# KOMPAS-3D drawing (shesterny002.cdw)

Views: View = Шестерня, Вид слева, Разрез Б-Б, Вид 12, Вид 13, Выносной элемент, Вид 16, Вид 17
Referenced files in C:\Program Files (x86)\ASCON\KOMPAS-3D V12\Sys\: spds.lcs
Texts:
  Шестерня
  Торцы зубъев закруглить
  Делительный диаметр
  Длина общей нормали
  Степень точности
  по ГОСТ 1643-81
  Коэффициент смещения
  Исходный контур
  Направление линии зуба
  Угол наклона зубьев
  Число зубьев
  Модуль
  ГОСТ 13755-81
  Левое
  Таблица параметров
  R0,3max
  *Размер для справок.
  HRC 28 ... 32.
  style from library
  Скрытая линия
  gliv
  Сталь 45 ГОСТ 1050-88
Dimensions and other numbers on the sheet: 70; 172,22; 161,1; 1; 4 фаски; 3,2; 2,5; 6,3; 147; 4; 2; 10; 45; 183,6; 25; 55,063 -0,07 -0,17; 8-В; +0,138; 25 50'31"; 31; 5; 8; 52; 43min; 0,4; 12,5; 1:1; 4,2; 0; 3; 6; 7; 9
